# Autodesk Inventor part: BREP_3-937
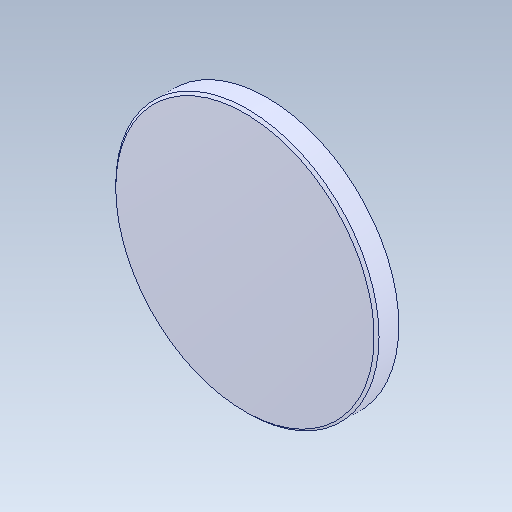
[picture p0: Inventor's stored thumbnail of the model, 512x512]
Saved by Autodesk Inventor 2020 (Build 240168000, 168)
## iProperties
Created: 2017-09
Part Number: BREP_3-937
Material: Générique
Document SubType Name: Modeling
Designer: bruno
Density: 1 g/cm^3
Appearance: Par défaut
Author: bruno
Sending System: SolidWorks 2016
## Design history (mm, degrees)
feature "Importée1"
node "Solide1"
